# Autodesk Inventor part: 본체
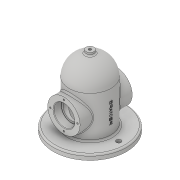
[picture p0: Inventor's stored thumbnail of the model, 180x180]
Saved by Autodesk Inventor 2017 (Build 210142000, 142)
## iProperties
Created: 2019-11
Part Number: 본체
Material: Generic
Document SubType Name: Modeling
Designer: 1-11-lg
Density: 1 g/cm^3
Appearance: Default
Author: 1-11-lg
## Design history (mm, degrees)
sketch "Sketch1"
  geometry: C1 r 70 at (0, 0); 1 further point
  constraints: 1 centre point, 1 coincident
  dimensions: "d0" = 140 diameter of C1
extrude "Extrusion1" new body sketch "Sketch1" distance "d1" = 10; taper "d2" = 0 deg
sketch "Sketch2"
  geometry: C1 r 70 at (0, 0) reference; C2 r 40 at (0, 0)
  constraints: 1 centre point, 1 coincident
  dimensions: "d3" = 80 diameter of C2
extrude "Extrusion2" join sketch "Sketch2" distance "d4" = 80; taper "d5" = 0 deg
sketch "Sketch3"
  geometry: L1 (90, 40)-(90, 0); L2 (90, 0)-(130, 0); L3 (90, -40)-(90, 40) reference; A1 r 40 centre (90, 0) between (130, 0) and (90, 40); 1 further point
  constraints: 4 end point, 2 point on circle, 1 centre point, 1 collinear, 1 horizontal, 1 horizontal alignment, 1 vertical
  dimensions: "d7" = 80 diameter of A1
revolve "Revolution1" sketch "Sketch3" stored, may be unused: angle "d8" = 90 deg
sketch "Sketch4"
  geometry: C1 r 70 at (0, 0) reference; C2 r 30 at (0, 0)
  constraints: 1 centre point, 1 coincident
  dimensions: "d9" = 60 diameter of C2
extrude "Extrusion3" cut sketch "Sketch4" distance "d10" = 90; taper "d11" = 0 deg
sketch "Sketch5"
  geometry: L1 (90, 0)-(120, 0); L2 (90, 30)-(90, 0); L3 (90, -30)-(90, 30) reference; A1 r 30 centre (90, 0) between (120, 0) and (90, 30); 1 further point
  constraints: 4 end point, 2 point on circle, 1 centre point, 1 collinear, 1 horizontal, 1 horizontal alignment, 1 vertical
  dimensions: "d12" = 60 diameter of A1
revolve "Revolution2" sketch "Sketch5" stored, may be unused: angle "d13" = 90 deg
workplane "Work Plane1"
sketch "Sketch6"
  geometry: L1 (-70, 0)-(70, 0) reference; C1 r 31 at (0, 50); 1 further point
  constraints: 1 centre point, 1 vertical alignment
  dimensions: "d15" = 62 diameter of C1; "d16" = 50 distance from line of L1 C1.centre
extrude "Extrusion4" join sketch "Sketch6" stored distance "d17" = 100; taper "d18" = 0 deg
mirror "Mirror1"
sketch "Sketch7"
  geometry: C1 r 31 at (0, 0) reference; C2 r 20 at (0, 0); 1 further point
  constraints: 1 centre point, 1 coincident
  dimensions: "d19" = 40 diameter of C2
extrude "Extrusion5" cut sketch "Sketch7" distance "d20" = 15; taper "d21" = 0 deg
sketch "Sketch8"
  geometry: L1 (0, 0)-(0, 26); C1 r 31 at (0, 0) reference; 2 further points
  constraints: 2 end point, 1 coincident, 1 vertical
  dimensions: "d22" = 26 distance of L1.start L1.end
hole "Hole1" sketch "Sketch8" at (0, 26) diameter "d23" = 3.242; stored, may be unused: countersink angle "d27" = 90 deg, drill point angle "d29" = 118 deg; dims "d24" = 8, "d25" = 4, "d26" = 2, "d28" = 10
pattern_circular "Circular Pattern1" dims angle "d31" = 360 deg
sketch "Sketch9"
  geometry: C1 r 20 at (0, 0) reference; C2 r 16.5 at (0, 0); 1 further point
  constraints: 1 centre point, 1 coincident
  dimensions: "d33" = 33 diameter of C2
extrude "Extrusion6" cut sketch "Sketch9" stored distance "d34" = 100; taper "d35" = 0 deg
sketch "Sketch10"
  geometry: C1 r 16.5 at (0, 0) reference; C2 r 31 at (0, 0) reference; C3 r 20 at (0, 0); 1 further point
  constraints: 1 centre point, 1 coincident
  dimensions: "d36" = 40 diameter of C3
extrude "Extrusion7" cut sketch "Sketch10" distance "d37" = 15; taper "d38" = 0 deg
sketch "Sketch11"
  geometry: L1 (0, 0)-(0, 26); C1 r 31 at (0, 0) reference; 2 further points
  constraints: 2 end point, 1 coincident, 1 vertical
  dimensions: "d39" = 26 distance of L1.start L1.end
hole "Hole2" sketch "Sketch11" at (0, 26) diameter "d40" = 3.242; stored, may be unused: countersink angle "d44" = 90 deg, drill point angle "d46" = 118 deg; dims "d41" = 8, "d42" = 4, "d43" = 2, "d45" = 10
pattern_circular "Circular Pattern2" dims angle "d48" = 360 deg
workplane "Work Plane2"
sketch "Sketch12"
  geometry: C1 r 7.5 at (0, 0); 1 further point
  constraints: 1 centre point, 1 coincident
  dimensions: "d51" = 15 diameter of C1
extrude "Extrusion8" join sketch "Sketch12" stored distance "d52" = 15; taper "d53" = 0 deg
sketch "Sketch13"
  geometry: C1 r 7.5 at (0, 0) reference; 1 further point
  constraints: 1 coincident
hole "Hole3" sketch "Sketch13" at (0, 0) diameter "d54" = 5.188; stored, may be unused: countersink angle "d58" = 90 deg, drill point angle "d60" = 118 deg; dims "d55" = 20, "d56" = 4, "d57" = 2, "d59" = 20
sketch "Sketch14"
  geometry: L1 (0, 0)-(-55, 0); L2 (0, 0)-(55, 0); C1 r 70 at (0, 0) reference; C2 r 4.5 at (-55, 0); C3 r 4.5 at (55, 0)
  constraints: 4 end point, 2 centre point, 2 coincident, 2 horizontal, 1 equal radius
  dimensions: "d61" = 55 distance of L1.start L1.end; "d62" = 55 distance of L1.start L2.end; "d63" = 9 diameter of C3
extrude "Extrusion9" cut sketch "Sketch14" stored distance "d64" = 15; taper "d65" = 0 deg
workplane "Work Plane3"
sketch "Sketch15"
  geometry: L1 (70.739, -3.002)-(29.261, -3.002); L2 (29.261, -3.002)-(29.261, 3.002); L3 (29.261, 3.002)-(70.739, 3.002); L4 (70.739, 3.002)-(70.739, -3.002); L5 (0, 70)-(0, -70) reference; L6 (50, -3.002)-(50, 3.002); L7 (70.739, 0)-(29.261, 0); 3 further points
  constraints: 6 midpoint, 4 end point, 1 horizontal alignment, 2 other
  dimensions: "d68" = 50 distance between parallel lines of L6 L5
emboss "Emboss1" sketch "Sketch15" dims "d2" = 0, "d69" = 0.5, "d70" = 0
chamfer "Chamfer1" distance "d71" = 1; stored, may be unused: second distance "d72" = 2, angle "d73" = 45 deg
fillet "Fillet1" dims "d74" = 0.3
fillet "Fillet2" dims "d75" = 3
fillet "Fillet3" dims "d76" = 3
fillet "Fillet4" dims "d77" = 3
body "Solid1"
other parameters: "d50" = -135, "d66" = 80.5
